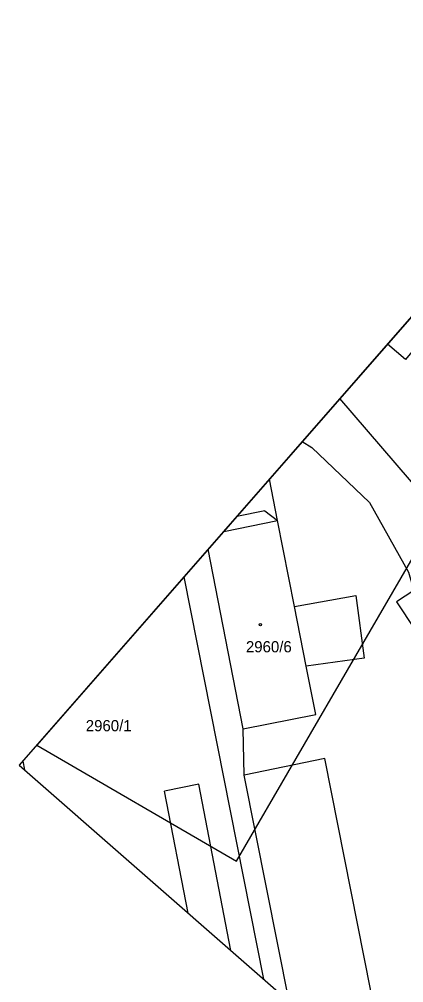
# Model space of a CAD drawing. Extents: x -620475 to -619963, y -1123010 to -1122510.
# Drawn here: x -620474.6 to -620416.3, y -1122766.6 to -1122620.5 of the extents above; entities that cross this region are included whole.
import ezdxf

# ---------------------------------------------------------------- set-up
doc = ezdxf.new("R2010")
doc.units = 0
for name, color, linetype in [('Hranice parcel', 7, 'Continuous'), ('Parcelní čísla', 7, 'Continuous'), ('Rámečky', 7, 'Continuous'), ('Rámečky-tisk', 7, 'Continuous'), ('Vnitřní kresba', 7, 'Continuous'), ('Značky budov', 7, 'Continuous')]:
    doc.layers.add(name, color=color, linetype=linetype)

msp = doc.modelspace()

# ---------------------------------------------------------------- linework, layer by layer
at = {"layer": 'Hranice parcel'}
for p, q in [((-620435.41, -1122696.52), (-620436.65, -1122690.22)), ((-620440.5, -1122735.14), (-620440.62, -1122728.09))]:
    msp.add_line(p, q, dxfattribs=at)
for points in [[(-620410.89, -1122660.77), (-620408.37, -1122662.86), (-620416.01, -1122672.06), (-620418.76, -1122669.77)], [(-620391.77, -1122717.74), (-620425.96, -1122678)], [(-620431.67, -1122684.53), (-620430.21, -1122685.42), (-620421.46, -1122693.76), (-620415.57, -1122704.35), (-620414.76, -1122707.13)], [(-620443.58, -1122698.14), (-620435.41, -1122696.52)], [(-620440.62, -1122728.09), (-620429.62, -1122725.94), (-620431.07, -1122718.59), (-620432.85, -1122709.54), (-620435.41, -1122696.52)], [(-620440.62, -1122728.09), (-620445.96, -1122700.85)], [(-620414.76, -1122707.13), (-620417.37, -1122708.84), (-620411.83, -1122717.24)], [(-620474.07, -1122732.99), (-620473.82, -1122734.31)], [(-620418.29, -1122782.89), (-620428.27, -1122732.6), (-620440.5, -1122735.14)], [(-620433.66, -1122769.44), (-620440.5, -1122735.14)]]:
    msp.add_lwpolyline(points, dxfattribs=at)
at = {"layer": 'Rámečky'}
msp.add_lwpolyline([(-620279.07, -1122510.07), (-620474.61, -1122733.62), (-620158.49, -1123010.14)], dxfattribs=at)
at = {"layer": 'Rámečky-tisk'}
msp.add_line((-620351.12, -1122592.44), (-620471.94, -1122730.56), dxfattribs=at)
for points in [[(-620279.07, -1122510.07), (-620474.61, -1122733.62), (-620158.49, -1123010.14)], [(-620471.94, -1122730.56), (-620441.66, -1122748.16), (-620351.12, -1122592.44)]]:
    msp.add_lwpolyline(points, dxfattribs=at)
at = {"layer": 'Vnitřní kresba'}
for p, q in [((-620437.36, -1122695.04), (-620441.6, -1122695.87)), ((-620437.36, -1122695.04), (-620435.41, -1122696.52)), ((-620449.62, -1122705.04), (-620437.54, -1122766.05)), ((-620432.85, -1122709.54), (-620423.56, -1122707.88)), ((-620423.56, -1122707.88), (-620422.3, -1122717.35)), ((-620422.3, -1122717.35), (-620431.07, -1122718.59)), ((-620447.35, -1122736.5), (-620452.59, -1122737.55)), ((-620448.97, -1122756.05), (-620452.59, -1122737.55)), ((-620442.49, -1122761.71), (-620447.35, -1122736.5))]:
    msp.add_line(p, q, dxfattribs=at)
at = {"layer": 'Značky budov'}
msp.add_circle((-620438.02, -1122712.31), 0.175, dxfattribs=at)

# ---------------------------------------------------------------- texts
at = {"layer": 'Parcelní čísla'}
for s, p in [('2960/6', (-620440.22, -1122716.49)), ('2960/1', (-620464.52, -1122728.46))]:
    msp.add_text(s, height=1.7, dxfattribs=at).set_placement(p)

doc.saveas('drawing.dxf')
